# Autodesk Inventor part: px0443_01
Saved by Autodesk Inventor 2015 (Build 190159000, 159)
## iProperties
Created: 2019-05
Part Number: px0443_01
Checked By: TraceParts S.A.
Material: Generic
Catalog Web Link: www.traceparts.com
Document SubType Name: Modeling
Designer: TraceParts
Density: 1 g/cm^3
Appearance: Default
Company: TraceParts S.A.
Author: TraceParts
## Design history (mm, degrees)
feature "px0443_01.ipt"
body "Solid1"
